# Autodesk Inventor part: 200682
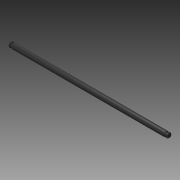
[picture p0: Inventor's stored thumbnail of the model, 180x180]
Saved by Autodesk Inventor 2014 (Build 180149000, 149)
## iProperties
Created: 2007-10
Part Number: 200682
Document SubType Name: Modeling
Designer: TH
Density: 7.85 g/cm^3
Mass: 382.443 g
Surface Area: 158.814 cm^2
Volume: 48.7189 cm^3
Material: Steel
Description: SUPPORT ROD
Appearance: Rubber - Black - Version 1.1
Component Category: Lower Component
Author: TH
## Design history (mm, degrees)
sketch "Sketch1"
  geometry: L1 (196.45, 0)-(-196.45, 0); L2 (-196.45, 0)-(-196.45, 3.455); L3 (-193.575, 6.33)-(-193.5, 6.33); L4 (-193.5, 6.33)-(-193.5, 4.218); L5 (-193.5, 4.218)-(-189.5, 4.218); L6 (-189.5, 4.218)-(-189.5, 6.33); L7 (-189.5, 6.33)-(189.5, 6.33); L8 (189.5, 6.33)-(189.5, 4.218); L9 (189.5, 4.218)-(193.5, 4.218); L10 (193.5, 4.218)-(193.5, 6.33); L11 (193.5, 6.33)-(193.575, 6.33); L12 (196.45, 3.455)-(196.45, 0); A1 r 2.875 centre (-193.575, 3.455) between (-193.575, 6.33) and (-196.45, 3.455); A2 r 2.875 centre (193.575, 3.455) between (196.45, 3.455) and (193.575, 6.33); 2 further points
  constraints: 24 end point, 7 parallel, 4 point on circle, 4 tangent, 2 centre point, 2 collinear, 2 perpendicular, 1 coincident, 1 equal radius, 1 horizontal, 1 midpoint
  dimensions: "d2" = 12.66 diameter of L7 L1 (= d5); "d4" = 8.436 diameter of L5 L1; "d5" = 12.66 diameter of L3 L1; "d7" = 8.436 diameter of L9 L1 (= d4); "d8" = 12.66 diameter of L11 L1 (= d5); "d15" = 2.875 radius of A1; "d21" = 2.95 distance between parallel lines of L4 L2; "d22" = 4 distance of L4.end L5.end; "d23" = 2.95 distance between parallel lines of L10 L12; "d24" = 4 distance of L8.end L9.end (= d22); "d29" = 387 distance between parallel lines of L10 L4
revolve "Revolution1" sketch "Sketch1" stored, may be unused: angle "d16" = 90 deg
chamfer "Chamfer1" distance "d17" = 2; stored, may be unused: second distance "d18" = 2, angle "d19" = 20 deg
fillet "Fillet1" dims "d20" = 0.5
chamfer "Chamfer2" distance "d25" = 2; stored, may be unused: second distance "d26" = 2, angle "d27" = 20 deg
workplane "Work Plane1"
split "Split1"
body "Solid1"
other parameters: "d28" = -114.45
